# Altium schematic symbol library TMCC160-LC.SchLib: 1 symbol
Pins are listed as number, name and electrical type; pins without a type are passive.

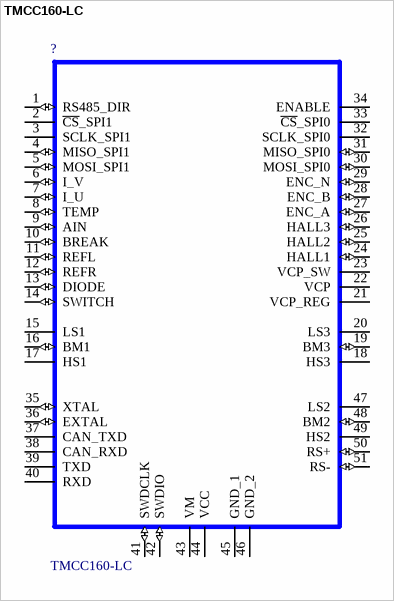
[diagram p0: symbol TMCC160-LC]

## TMCC160-LC
designator ?
TMCC160 motionCookie™microsystem with 3-Phase BLDC/PMSM gate driver for up to 24V and 1A gate current with CAN, Hall, RS485, SPI, UART; LGA51; Manufacturer: TRINAMIC; Geometry.Height: 1.4mm
footprint TMCC160_COOKIE
pins: 1 RS485_DIR (io), 2 ~{CS}_SPI1, 3 SCLK_SPI1, 4 MISO_SPI1 (io), 5 MOSI_SPI1 (io), 6 I_V (io), 7 I_U (io), 8 TEMP (io), 9 AIN (io), 10 BREAK (io), 11 REFL (io), 12 REFR (io), 13 DIODE (io), 14 SWITCH (io), 15 LS1, 16 BM1 (io), 17 HS1, 18 HS3, 19 BM3 (io), 20 LS3, 21 VCP_REG (power), 22 VCP (power), 23 VCP_SW (power), 24 HALL1 (io), 25 HALL2 (io), 26 HALL3 (io), 27 ENC_A (io), 28 ENC_B (io), 29 ENC_N (io), 30 MOSI_SPI0 (io), 31 MISO_SPI0 (io), 32 SCLK_SPI0, 33 ~{CS}_SPI0, 34 ENABLE, 35 XTAL (io), 36 EXTAL (io), 37 CAN_TXD, 38 CAN_RXD, 39 TXD, 40 RXD, 41 SWDCLK (io), 42 SWDIO (io), 43 VM, 44 VCC, 45 GND_1, 46 GND_2, 47 LS2, 48 BM2 (io), 49 HS2, 50 RS+ (io), 51 RS- (io)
